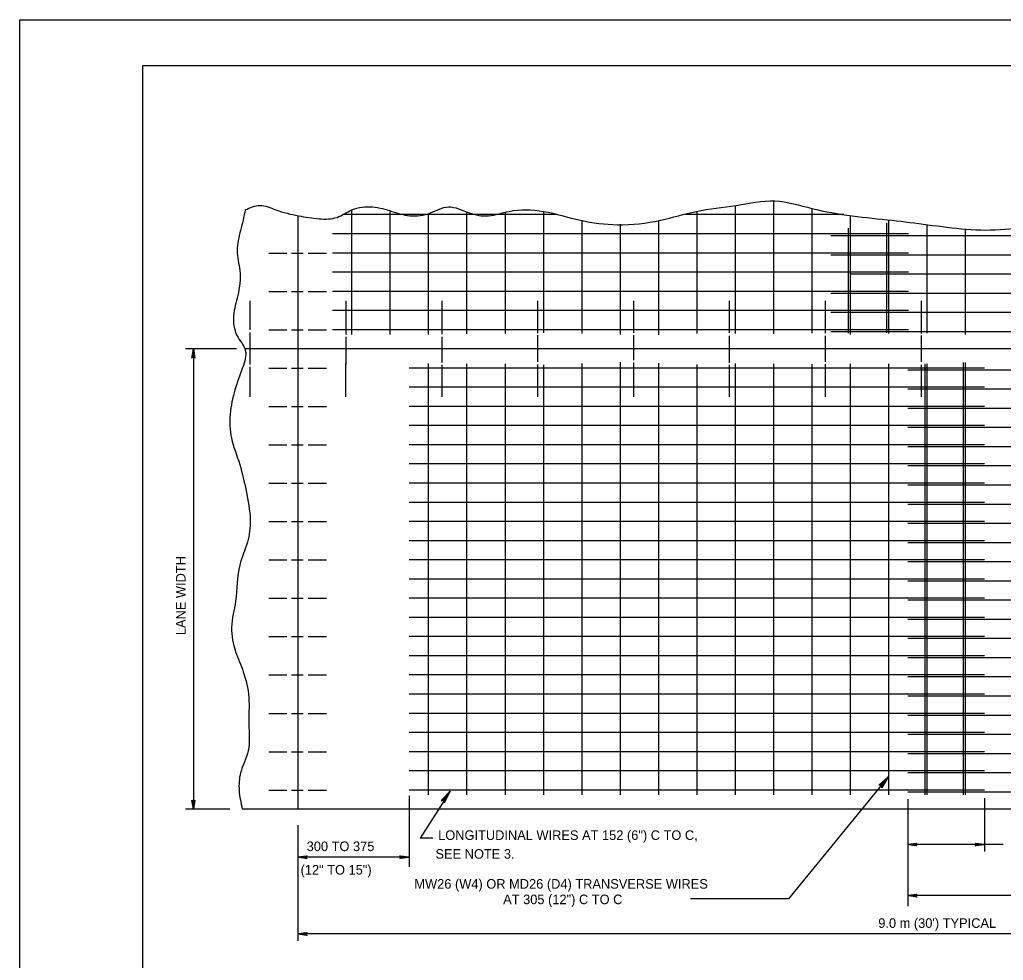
# Model space of a CAD drawing. Extents: x 638703 to 639608, y 298343 to 298937.
# Drawn here: x 638702.9 to 639023.6, y 298630.1 to 298936.6 of the extents above; entities that cross this region are included whole.
import ezdxf

# ---------------------------------------------------------------- set-up
doc = ezdxf.new("R2010")
doc.units = 0
for name, color, linetype in [('1', 7, 'Continuous'), ('2', 7, 'Continuous'), ('3', 7, 'Continuous'), ('PLT-BNDY', 7, 'Continuous')]:
    doc.layers.add(name, color=color, linetype=linetype)

msp = doc.modelspace()

# ---------------------------------------------------------------- linework, layer by layer
at = {"layer": '1'}
msp.add_lwpolyline([(639528.936, 298357.638375), (639528.936, 298921.638375), (638742.936, 298921.638375), (638742.936, 298357.638375), (639528.936, 298357.638375), (639528.936, 298383.997375), (639328.936, 298383.997375), (639328.936, 298448.674875), (639528.936, 298448.674875), (639528.936, 298477.638375), (639328.936, 298477.638375), (639328.936, 298357.638375), (639407.7375, 298357.638375), (639407.7375, 298383.997375), (639407.7375, 298357.638375), (639484.7375, 298357.638375), (639484.7375, 298383.997375), (639484.7375, 298371.680875), (639528.936, 298371.680875)], dxfattribs=at)
at = {"layer": '2'}
for p, q in [((638811.1325, 298874.433625), (638811.1325, 298834.085875)), ((638936.1325, 298875.900375), (638936.1325, 298834.383625)), ((638948.6325, 298877.508625), (638948.6325, 298834.283625)), ((638961.1325, 298874.969125), (638961.1325, 298834.462875)), ((638793.622, 298872.596125), (638793.622, 298679.356625)), ((638878.0345, 298873.106625), (638808.27, 298873.106625)), ((638823.6325, 298874.056625), (638823.6325, 298834.085875)), ((638836.1325, 298873.500375), (638836.1325, 298834.085875)), ((638848.6325, 298873.877375), (638848.6325, 298834.264875)), ((638861.1325, 298873.819125), (638861.1325, 298834.344125)), ((638873.6325, 298874.096125), (638873.6325, 298834.562875)), ((638886.1325, 298871.298375), (638886.1325, 298834.383625)), ((638971.622, 298873.106625), (638919.88875, 298873.106625)), ((638923.6325, 298873.917125), (638923.6325, 298834.383625)), ((638973.6325, 298872.806625), (638973.6325, 298834.085875)), ((638986.1325, 298871.379625), (638986.1325, 298834.362875)), ((638898.6325, 298870.010875), (638898.6325, 298834.006625)), ((638911.1325, 298871.121125), (638911.1325, 298833.927375)), ((638972.9825, 298868.700375), (638972.9825, 298834.462875)), ((638985.4825, 298870.427375), (638985.4825, 298834.562875)), ((638998.6325, 298869.810875), (638998.6325, 298834.462875)), ((639011.1325, 298868.244125), (639011.1325, 298834.085875)), ((638992.67625, 298866.856625), (638804.92825, 298866.856625)), ((639132.068, 298866.206625), (638967.3845, 298866.206625)), ((638784.204, 298860.606625), (638790.0415, 298860.606625)), ((638791.52075, 298860.606625), (638795.38525, 298860.606625)), ((638796.95825, 298860.606625), (638802.954, 298860.606625)), ((638992.67625, 298860.606625), (638804.92825, 298860.606625)), ((639132.068, 298859.956625), (638967.3845, 298859.956625)), ((638992.67625, 298854.356625), (638804.92825, 298854.356625)), ((639132.068, 298853.706625), (638973.6325, 298853.706625)), ((638784.204, 298848.106625), (638790.0415, 298848.106625)), ((638791.52075, 298848.106625), (638795.38525, 298848.106625)), ((638796.95825, 298848.106625), (638802.954, 298848.106625)), ((638992.67625, 298848.106625), (638804.92825, 298848.106625)), ((639132.068, 298847.456625), (638967.3845, 298847.456625)), ((638777.997, 298844.981625), (638777.997, 298835.612875)), ((638809.247, 298844.981625), (638809.247, 298834.085875)), ((638840.497, 298844.981625), (638840.497, 298834.164875)), ((638871.747, 298844.981625), (638871.747, 298834.483625)), ((638902.997, 298844.981625), (638902.997, 298834.642125)), ((638934.247, 298844.981625), (638934.247, 298834.562875)), ((638965.497, 298844.981625), (638965.497, 298834.502375)), ((638996.747, 298844.981625), (638996.747, 298834.423375)), ((638992.67625, 298841.856625), (638804.92825, 298841.856625)), ((639132.068, 298841.206625), (638967.3845, 298841.206625)), ((638777.997, 298834.700375), (638777.997, 298824.306625)), ((638784.204, 298835.606625), (638790.0415, 298835.606625)), ((638791.52075, 298835.606625), (638795.38525, 298835.606625)), ((638796.95825, 298835.606625), (638802.954, 298835.606625)), ((638992.67625, 298835.606625), (638804.92825, 298835.606625)), ((638809.247, 298833.331625), (638809.247, 298824.248375)), ((638840.497, 298833.252375), (638840.497, 298824.842125)), ((638871.747, 298833.808625), (638871.747, 298825.160875)), ((638902.997, 298833.808625), (638902.997, 298825.696125)), ((638934.247, 298833.650375), (638934.247, 298824.783625)), ((638965.497, 298833.669125), (638965.497, 298825.179625)), ((639132.068, 298834.956625), (638967.3845, 298834.956625)), ((638996.747, 298833.748375), (638996.747, 298825.100375)), ((638773.6555, 298829.356625), (638757.01175, 298829.356625)), ((638759.57, 298829.356625), (638759.57, 298679.356625)), ((639227.8345, 298829.356625), (638776.5305, 298829.356625)), ((638777.997, 298823.473375), (638777.997, 298813.731625)), ((638784.204, 298823.106625), (638790.0415, 298823.106625)), ((638791.52075, 298823.106625), (638795.38525, 298823.106625)), ((638796.95825, 298823.106625), (638802.954, 298823.106625)), ((638809.247, 298813.731625), (638809.247, 298824.627375)), ((639017.3825, 298823.106625), (638829.8825, 298823.106625)), ((638836.1325, 298824.604625), (638836.1325, 298684.062875)), ((638840.497, 298824.167125), (638840.497, 298813.731625)), ((638848.6325, 298824.504625), (638848.6325, 298684.062875)), ((638861.1325, 298824.504625), (638861.1325, 298684.062875)), ((638871.747, 298824.327375), (638871.747, 298813.731625)), ((638873.6325, 298824.167125), (638873.6325, 298684.062875)), ((638886.1325, 298824.623375), (638886.1325, 298684.062875)), ((638898.6325, 298825.079625), (638898.6325, 298684.062875)), ((638902.997, 298824.942125), (638902.997, 298813.731625)), ((638911.1325, 298824.723375), (638911.1325, 298684.062875)), ((638923.6325, 298824.267125), (638923.6325, 298684.062875)), ((638934.247, 298824.187875), (638934.247, 298813.731625)), ((638936.1325, 298824.623375), (638936.1325, 298684.062875)), ((638948.6325, 298824.446125), (638948.6325, 298684.062875)), ((638961.1325, 298824.346125), (638961.1325, 298684.062875)), ((638965.497, 298824.346125), (638965.497, 298813.731625)), ((638973.6325, 298824.446125), (638973.6325, 298684.062875)), ((638986.1325, 298824.525375), (638986.1325, 298684.062875)), ((638996.747, 298824.187875), (638996.747, 298813.731625)), ((638997.9825, 298824.446125), (638997.9825, 298684.062875)), ((638998.6325, 298824.446125), (638998.6325, 298684.062875)), ((639010.4825, 298824.902375), (639010.4825, 298684.062875)), ((639011.1325, 298824.902375), (639011.1325, 298684.062875)), ((639159.07, 298822.456625), (638992.3825, 298822.456625)), ((639017.3825, 298816.856625), (638829.8825, 298816.856625)), ((639159.07, 298816.206625), (638992.3825, 298816.206625)), ((638784.204, 298810.606625), (638790.0415, 298810.606625)), ((638791.52075, 298810.606625), (638795.38525, 298810.606625)), ((638796.95825, 298810.606625), (638802.954, 298810.606625)), ((639017.3825, 298810.606625), (638829.8825, 298810.606625)), ((639159.07, 298809.956625), (638992.3825, 298809.956625)), ((639017.3825, 298804.356625), (638829.8825, 298804.356625)), ((639159.07, 298803.706625), (638992.3825, 298803.706625)), ((638784.204, 298798.106625), (638790.0415, 298798.106625)), ((638791.52075, 298798.106625), (638795.38525, 298798.106625)), ((638796.95825, 298798.106625), (638802.954, 298798.106625)), ((639017.3825, 298798.106625), (638829.8825, 298798.106625)), ((639159.07, 298797.456625), (638992.3825, 298797.456625)), ((639017.3825, 298791.856625), (638829.8825, 298791.856625)), ((639159.07, 298791.206625), (638992.3825, 298791.206625)), ((638784.204, 298785.606625), (638790.0415, 298785.606625)), ((638791.52075, 298785.606625), (638795.38525, 298785.606625)), ((638796.95825, 298785.606625), (638802.954, 298785.606625)), ((639017.3825, 298785.606625), (638829.8825, 298785.606625)), ((639159.07, 298784.956625), (638992.3825, 298784.956625)), ((639017.3825, 298779.356625), (638829.8825, 298779.356625)), ((639159.07, 298778.706625), (638992.3825, 298778.706625)), ((638784.204, 298773.106625), (638790.0415, 298773.106625)), ((638791.52075, 298773.106625), (638795.38525, 298773.106625)), ((638796.95825, 298773.106625), (638802.954, 298773.106625)), ((639017.3825, 298773.106625), (638829.8825, 298773.106625)), ((639159.07, 298772.456625), (638992.3825, 298772.456625)), ((639017.3825, 298766.856625), (638829.8825, 298766.856625)), ((639159.07, 298766.206625), (638992.3825, 298766.206625)), ((638784.204, 298760.606625), (638790.0415, 298760.606625)), ((638791.52075, 298760.606625), (638795.38525, 298760.606625)), ((638796.95825, 298760.606625), (638802.954, 298760.606625)), ((639017.3825, 298760.606625), (638829.8825, 298760.606625)), ((639159.07, 298759.956625), (638992.3825, 298759.956625)), ((639017.3825, 298754.356625), (638829.8825, 298754.356625)), ((639159.07, 298753.706625), (638992.3825, 298753.706625)), ((638784.204, 298748.106625), (638790.0415, 298748.106625)), ((638791.52075, 298748.106625), (638795.38525, 298748.106625)), ((638796.95825, 298748.106625), (638802.954, 298748.106625)), ((639017.3825, 298748.106625), (638829.8825, 298748.106625)), ((639159.07, 298747.456625), (638992.3825, 298747.456625)), ((639017.3825, 298741.856625), (638829.8825, 298741.856625)), ((639159.07, 298741.206625), (638992.3825, 298741.206625)), ((638784.204, 298735.606625), (638790.0415, 298735.606625)), ((638791.52075, 298735.606625), (638795.38525, 298735.606625)), ((638796.95825, 298735.606625), (638802.954, 298735.606625)), ((639017.3825, 298735.606625), (638829.8825, 298735.606625)), ((639159.07, 298734.956625), (638992.3825, 298734.956625)), ((639017.3825, 298729.356625), (638829.8825, 298729.356625)), ((639159.07, 298728.706625), (638992.3825, 298728.706625)), ((638784.204, 298723.106625), (638790.0415, 298723.106625)), ((638791.52075, 298723.106625), (638795.38525, 298723.106625)), ((638796.95825, 298723.106625), (638802.954, 298723.106625)), ((639017.3825, 298723.106625), (638829.8825, 298723.106625)), ((639159.07, 298722.456625), (638992.3825, 298722.456625)), ((639017.3825, 298716.856625), (638829.8825, 298716.856625)), ((639159.07, 298716.206625), (638992.3825, 298716.206625)), ((638784.20325, 298710.606625), (638790.0365, 298710.606625)), ((638791.51375, 298710.606625), (638795.3825, 298710.606625)), ((638793.622, 298710.606625), (638793.622, 298710.606625)), ((638793.622, 298710.606625), (638793.622, 298710.606625)), ((638793.622, 298710.606625), (638793.622, 298710.606625)), ((638793.622, 298710.606625), (638793.622, 298710.606625)), ((638793.622, 298710.606625), (638793.622, 298710.606625)), ((638793.622, 298710.606625), (638793.622, 298710.606625)), ((638793.622, 298710.606625), (638793.622, 298710.606625)), ((638793.622, 298710.606625), (638793.622, 298710.606625)), ((638793.622, 298710.606625), (638793.622, 298710.606625)), ((638793.622, 298710.606625), (638793.622, 298710.606625)), ((638793.622, 298710.606625), (638793.622, 298710.606625)), ((638793.622, 298710.606625), (638793.622, 298710.606625)), ((638793.622, 298710.606625), (638793.622, 298710.606625)), ((638796.96575, 298710.606625), (638802.95325, 298710.606625)), ((639017.3825, 298710.606625), (638829.8825, 298710.606625)), ((639159.07, 298709.956625), (638992.3825, 298709.956625)), ((639017.3825, 298704.356625), (638829.8825, 298704.356625)), ((639159.07, 298703.706625), (638992.3825, 298703.706625)), ((638784.2045, 298698.106625), (638790.0315, 298698.106625)), ((638791.5065, 298698.106625), (638795.3815, 298698.106625)), ((638793.62325, 298698.106625), (638793.62325, 298698.106625)), ((638793.62325, 298698.106625), (638793.62325, 298698.106625)), ((638793.62325, 298698.106625), (638793.62325, 298698.106625)), ((638793.62325, 298698.106625), (638793.62325, 298698.106625)), ((638793.62325, 298698.106625), (638793.62325, 298698.106625)), ((638793.62325, 298698.106625), (638793.62325, 298698.106625)), ((638793.62325, 298698.106625), (638793.62325, 298698.106625)), ((638793.62325, 298698.106625), (638793.62325, 298698.106625)), ((638793.62325, 298698.106625), (638793.62325, 298698.106625)), ((638793.62325, 298698.106625), (638793.62325, 298698.106625)), ((638793.62325, 298698.106625), (638793.62325, 298698.106625)), ((638793.62325, 298698.106625), (638793.62325, 298698.106625)), ((638793.62325, 298698.106625), (638793.62325, 298698.106625)), ((638793.62325, 298698.106625), (638793.62325, 298698.106625)), ((638796.97325, 298698.106625), (638802.9545, 298698.106625)), ((639017.3825, 298698.106625), (638829.8825, 298698.106625)), ((639159.07, 298697.456625), (638992.3825, 298697.456625)), ((639017.3825, 298691.856625), (638829.8825, 298691.856625)), ((638986.13875, 298690.039875), (638953.5155, 298650.218875)), ((639159.07, 298691.206625), (638992.3825, 298691.206625)), ((638784.20375, 298685.606625), (638790.0265, 298685.606625)), ((638791.4995, 298685.606625), (638795.37875, 298685.606625)), ((638793.6225, 298685.606625), (638793.6225, 298685.606625)), ((638793.6225, 298685.606625), (638793.6225, 298685.606625)), ((638793.6225, 298685.606625), (638793.6225, 298685.606625)), ((638793.6225, 298685.606625), (638793.6225, 298685.606625)), ((638793.6225, 298685.606625), (638793.6225, 298685.606625)), ((638793.6225, 298685.606625), (638793.6225, 298685.606625)), ((638793.6225, 298685.606625), (638793.6225, 298685.606625)), ((638793.6225, 298685.606625), (638793.6225, 298685.606625)), ((638793.6225, 298685.606625), (638793.6225, 298685.606625)), ((638793.6225, 298685.606625), (638793.6225, 298685.606625)), ((638793.6225, 298685.606625), (638793.6225, 298685.606625)), ((638793.6225, 298685.606625), (638793.6225, 298685.606625)), ((638793.6225, 298685.606625), (638793.6225, 298685.606625)), ((638793.6225, 298685.606625), (638793.6225, 298685.606625)), ((638793.6225, 298685.606625), (638793.6225, 298685.606625)), ((638796.98075, 298685.606625), (638802.95375, 298685.606625)), ((639017.3825, 298685.606625), (638829.8825, 298685.606625)), ((638843.27, 298685.237875), (638833.45925, 298669.881625)), ((638829.8825, 298683.746125), (638829.8825, 298660.558625)), ((639159.07, 298684.906625), (638992.3825, 298684.906625)), ((638992.3825, 298682.694125), (638992.3825, 298647.764875)), ((639017.3825, 298682.992125), (639017.3825, 298665.552625)), ((638771.45325, 298679.356625), (638757.01175, 298679.356625)), ((639227.43475, 298679.356625), (638775.4805, 298679.356625)), ((638793.622, 298674.142125), (638793.622, 298636.517125)), ((638837.6055, 298669.881625), (638833.45925, 298669.881625)), ((639017.3825, 298667.873875), (638992.3825, 298667.873875)), ((639023.49075, 298667.873875), (639017.3825, 298667.873875)), ((638829.8825, 298663.731625), (638793.622, 298663.731625)), ((638953.5155, 298650.218875), (638921.561, 298650.218875)), ((639196.57, 298651.231625), (638992.3825, 298651.231625)), ((639196.57, 298638.731625), (638793.622, 298638.731625))]:
    msp.add_line(p, q, dxfattribs=at)
for points in [[(638759.21375, 298826.519125), (638759.42, 298826.625375), (638759.57, 298829.356625), (638759.21375, 298826.519125), (638759.08875, 298826.373375), (638759.57, 298829.356625), (638759.7055, 298826.627375), (638759.9075, 298826.527375), (638759.57, 298829.356625), (638760.045, 298826.373375), (638759.9075, 298826.527375)], [(638983.23375, 298687.283625), (638983.5515, 298687.213625), (638986.13875, 298690.039875), (638983.23375, 298687.283625), (638982.97125, 298687.234375), (638986.13875, 298690.039875), (638983.86375, 298686.963125), (638983.995, 298686.674375), (638986.13875, 298690.039875), (638984.00375, 298686.388375), (638983.995, 298686.674375)], [(638841.4255, 298681.684125), (638841.273, 298681.969875), (638843.27, 298685.237875), (638841.4255, 298681.684125), (638841.45375, 298681.416875), (638843.27, 298685.237875), (638840.944, 298682.197125), (638840.63275, 298682.244375), (638843.27, 298685.237875), (638840.3515, 298682.174375), (638840.63275, 298682.244375)], [(638759.92625, 298682.194125), (638759.72, 298682.087875), (638759.57, 298679.356625), (638759.92625, 298682.194125), (638760.05125, 298682.339875), (638759.57, 298679.356625), (638759.4345, 298682.085875), (638759.2325, 298682.185875), (638759.57, 298679.356625), (638759.095, 298682.339875), (638759.2325, 298682.185875)], [(638995.22, 298667.517625), (638995.11375, 298667.723875), (638992.3825, 298667.873875), (638995.22, 298667.517625), (638995.36575, 298667.392625), (638992.3825, 298667.873875), (638995.11175, 298668.009375), (638995.21175, 298668.211375), (638992.3825, 298667.873875), (638995.36575, 298668.348875), (638995.21175, 298668.211375)], [(639014.545, 298668.230125), (639014.65125, 298668.023875), (639017.3825, 298667.873875), (639014.545, 298668.230125), (639014.39925, 298668.355125), (639017.3825, 298667.873875), (639014.65325, 298667.738375), (639014.55325, 298667.536375), (639017.3825, 298667.873875), (639014.39925, 298667.398875), (639014.55325, 298667.536375)], [(638796.4595, 298663.375375), (638796.35325, 298663.581625), (638793.622, 298663.731625), (638796.4595, 298663.375375), (638796.60525, 298663.250375), (638793.622, 298663.731625), (638796.35125, 298663.867125), (638796.45125, 298664.069125), (638793.622, 298663.731625), (638796.60525, 298664.206625), (638796.45125, 298664.069125)], [(638827.045, 298664.087875), (638827.15125, 298663.881625), (638829.8825, 298663.731625), (638827.045, 298664.087875), (638826.89925, 298664.212875), (638829.8825, 298663.731625), (638827.15325, 298663.596125), (638827.05325, 298663.394125), (638829.8825, 298663.731625), (638826.89925, 298663.256625), (638827.05325, 298663.394125)], [(638995.22, 298650.875375), (638995.11375, 298651.081625), (638992.3825, 298651.231625), (638995.22, 298650.875375), (638995.36575, 298650.750375), (638992.3825, 298651.231625), (638995.11175, 298651.367125), (638995.21175, 298651.569125), (638992.3825, 298651.231625), (638995.36575, 298651.706625), (638995.21175, 298651.569125)], [(638796.4595, 298638.375375), (638796.35325, 298638.581625), (638793.622, 298638.731625), (638796.4595, 298638.375375), (638796.60525, 298638.250375), (638793.622, 298638.731625), (638796.35125, 298638.867125), (638796.45125, 298639.069125), (638793.622, 298638.731625), (638796.60525, 298639.206625), (638796.45125, 298639.069125)]]:
    msp.add_lwpolyline(points, dxfattribs=at)
for points in [[(638776.49075, 298874.669125), (638781.2325, 298876.119125), (638786.445, 298874.669125), (638793.8075, 298872.727375), (638800.593, 298871.754625), (638806.3845, 298872.231625), (638811.22425, 298874.652375), (638818.0095, 298875.623375), (638824.297, 298874.175375), (638830.08875, 298872.727375), (638836.872, 298873.700375), (638842.66575, 298875.623375), (638849.44925, 298873.700375), (638855.73675, 298872.727375), (638862.50125, 298874.175375), (638873.6305, 298874.175375), (638885.7305, 298871.279625), (638897.8095, 298869.831625), (638911.8555, 298871.279625), (638923.4595, 298874.175375), (638936.51175, 298876.119125), (638949.08675, 298877.567125), (638961.18675, 298875.148375), (638974.24075, 298872.727375), (638987.31175, 298871.279625), (638998.91575, 298869.831625), (639011.493, 298868.362875), (639024.068, 298868.362875), (639036.645, 298870.306625), (639048.745, 298872.231625), (639062.293, 298874.652375), (639074.37425, 298876.596125), (639086.94925, 298878.044125), (639098.57425, 298877.567125), (639112.122, 298876.596125), (639124.20325, 298874.652375), (639136.30325, 298871.754625), (639149.3555, 298869.831625), (639161.4555, 298869.831625), (639174.0325, 298871.754625), (639187.10325, 298874.175375), (639198.21175, 298875.623375), (639227.687, 298876.508625)], [(638776.49075, 298874.669125), (638774.92425, 298867.967125), (638773.793, 298861.421125), (638774.68675, 298854.875375), (638774.01175, 298846.742125), (638772.66375, 298840.196125), (638773.793, 298833.650375), (638776.49075, 298828.908625), (638775.59925, 298823.275375), (638773.12, 298816.054625), (638771.5325, 298808.139875), (638771.98875, 298800.246125), (638774.68675, 298791.656625), (638776.72825, 298783.087875), (638778.07825, 298773.604625), (638777.1845, 298766.364875), (638774.68675, 298758.925375), (638773.33675, 298747.183625), (638771.98875, 298738.594125), (638773.33675, 298730.698375), (638775.81575, 298724.152375), (638777.622, 298715.802375), (638777.622, 298706.994125), (638777.40325, 298698.404625), (638774.92425, 298691.185875), (638774.468, 298685.552375), (638775.4805, 298679.356625)]]:
    msp.add_spline(points, degree=3, dxfattribs=at)
at = {"layer": 'PLT-BNDY'}
msp.add_lwpolyline([(638702.936, 298936.638375), (639543.936, 298936.638375), (639543.936, 298342.638375), (638702.936, 298342.638375)], close=True, dxfattribs=at)

# ---------------------------------------------------------------- texts
at = {"layer": '1'}
msp.add_text('(12" TO 15")', height=3.1249995, dxfattribs=at).set_placement((638794.493357, 298658.072125))
at = {"layer": '3'}
msp.add_text('LANE WIDTH', height=3.1249995, rotation=90, dxfattribs=at).set_placement((638757.02075, 298736.086875))
for s, p in [('LONGITUDINAL WIRES AT 152 (6") C TO C,', (638839.343, 298669.356625)), ('300 TO 375', (638796.488274, 298665.722375)), ('SEE NOTE 3.', (638838.46375, 298663.244125)), ('MW26 (W4) OR MD26 (D4) TRANSVERSE WIRES', (638831.5905, 298653.475375)), ('AT 305 (12") C TO C', (638860.52825, 298648.425125)), ("9.0 m (30') TYPICAL", (638982.79675, 298640.706625))]:
    msp.add_text(s, height=3.1249995, dxfattribs=at).set_placement(p)

doc.saveas('drawing.dxf')
